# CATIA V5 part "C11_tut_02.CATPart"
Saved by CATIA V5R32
Part number: Part2
Material "Grey Blue": density 7860 kg/m3, Young's modulus 2e+11 Pa, Poisson ratio 0.266
Bounding box of the stored display mesh (mm): x 0 to 175, y -36.636 to 105, z 0 to 36.66
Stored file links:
  D:\PROJECTS\Project 2022\CATIA V5 6R 2022\Resources\Tutorial Files\c11_catia_v5_6r2022_tut\C11_tut_02.CATPart
  C:\Program Files\Dassault Systemes\B32\win_b64\startup\materials\brushed_metal2.jpg
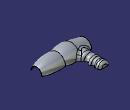
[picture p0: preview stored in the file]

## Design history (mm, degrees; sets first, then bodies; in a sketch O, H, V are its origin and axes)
Body1 (main body), material "Grey Blue"
  Plane1: type Offset, RefPlane yz-plane, Offset 50
  Set1
    Plane2: type Offset, RefPlane yz-plane, Offset 100 {= Plane1.Offset+`Plane2.Relative Offset`}
    Plane3: type Offset, RefPlane yz-plane, Offset 175
  Sketch1 on yz-plane, origin (0, 0, 0), H (0, 1, 0), V (0, 0, 1)
    arc A1 centre (0, 0) radius 25 from (25, 0) to (-25, 0) ccw
    point P1 (-25, 0)
    radius A1 = 25
  Sketch2 on Plane1, origin (50, 0, 0), H (0, 1, 0), V (0, 0, 1)
    arc A1 centre (0, 0) radius 35 from (35, 0) to (-35, 0) ccw
    point P1 (-35, 0)
    radius A1 = 35
  Sketch3 on Plane2, origin (100, 0, 0), H (0, 1, 0), V (0, 0, 1)
    arc A1 centre (0, 0) radius 30 from (30, 0) to (-30, 0) ccw
    point P1 (-30, 0)
    radius A1 = 30
  Sketch4 on Plane3, origin (175, 0, 0), H (0, 1, 0), V (0, 0, 1)
    arc A1 centre (0, 0) radius 20 from (20, 0) to (-20, 0) ccw
    point P1 (-20, 0)
    radius A1 = 20
  Sketch5 on xy-plane, origin (0, 0, 0), H (1, 0, 0), V (0, 1, 0)
    point P1 (0, -25)
    line L1 (0, -25) -> (50, -35)
    point P2 (50, -35)
    reference projected point E1 (50, -35) from Sketch2.P1
    reference projected point E2 (0, -25) from Sketch1.P1
    arc A1 centre (66.816, 49.3399) radius 86 from (50, -35) to (100, -30) ccw
    point P4 (100, -30)
    reference projected point E3 (100, -30) from Sketch3.P1
    arc A2 centre (121.7543, 93.0924) radius 125 from (100, -30) to (175, -20) ccw
    point P6 (175, -20)
    reference projected point E4 (175, -20) from Sketch4.P1
    radius A1 = 86
    radius A2 = 125
    coincidence: P1 V, P2 E1, P1 E2, P4 E3, E4 P6
  Sketch6 on xy-plane, origin (0, 0, 0), H (1, 0, 0), V (0, 1, 0)
    arc A1 centre (121.7543, -93.0924) radius 125 from (100, 30) to (175, 20) cw
    arc A2 centre (66.816, -49.3399) radius 86 from (50, 35) to (100, 30) cw
    line L1 (0, 25) -> (50, 35)
    fix: A1, L1, A2
  Loft1: Sections (Sketch1; Sketch2; Sketch3; Sketch4), Guides (Sketch5; Sketch6)
  Sketch7 on xy-plane, origin (0, 0, 0), H (1, 0, 0), V (0, 1, 0)
    point P1 (15, 105)
    line L1 (15, 105) -> (15, 0)
    point P2 (15, 0)
    point P3 (15, 105)
    distance H P1 = 105
    distance V L1 = 15
    coincidence: P2 H, P3 P1
    vertical: L1 V
  Plane4: type Normal, Curve Sketch7, RefPoint Sketch7.P3, Ratio 0
  Sketch8 on Plane4, origin (0, 105, 0), H (1, 0, 0), V (0, 0, 1)
    arc A1 centre (32.5, 0) radius 17.5 from (15, 0) to (50, 0) cw
    point P1 (32.5, 0)
    point P2 (15, 0)
    point P3 (50, 0)
    reference projected line E1 (0, 0) -> (-50, 0) from edge of Loft1
    reference projected point E2 (15, 0) from Sketch7.P2
    radius A1 = 17.5
    coincidence: P2 H, P3 H, P1 E1, E2 P2
  Sketch9 on xy-plane, origin (0, 0, 0), H (1, 0, 0), V (0, 1, 0)
    line L1 (50, 105) -> (51.989, 90.8478)
    point P1 (50, 105)
    arc A1 centre (45.0571, 89.8736) radius 7 from (51.989, 90.8478) to (49.6106, 84.5571) cw
    arc A2 centre (53.5135, 80) radius 6 from (49.6106, 84.5571) to (51.6373, 74.3009) ccw
    point P5 (53.5135, 80)
    point P6 (51.6373, 74.3009)
    arc A3 centre (50.1519, 69.7891) radius 4.75 from (51.6373, 74.3009) to (52.3972, 65.6033) cw
    point P8 (51.6373, 74.3009)
    arc A4 centre (56.6515, 57.6723) radius 9 from (52.3972, 65.6033) to (52.5866, 49.6425) ccw
    point P10 (56.6515, 57.6723)
    arc A5 centre (47.1667, 38.9362) radius 12 from (52.5866, 49.6425) to (59.0499, 40.6063) cw
    construction line L2 (50, 105) -> (61.1145, 25.9165)
    line L3 (59.0499, 40.6063) -> (64.9839, -1.6159)
    reference projected point E1 (50, 105) from Sketch8.P3
    axis line L4 (15, 105) -> (65.4512, 105)
    point P16 (15, 105)
    radius A1 = 7
    radius A2 = 6
    radius A3 = 4.75
    radius A4 = 9
    radius A5 = 12
    distance P5 P1 V = 25
    angle L4 L1 = 82
    distance P1 P16 = 35
    tangency: A2 A1, A3 L2, A3 A2, A3 A4, A5 A4, A5 L2, L3 A5, L3 L2, A1 L1
    coincidence: P8 A2, L2 L1, P5 L2, P8 P6, P10 L2, P1 E1
    horizontal: L4 H
  Loft2: Sections Sketch8, Guides (Sketch9; Sketch7)
  Trim1: Trimmed (Loft1; Loft2)
  Line1: type PtPt, FirstPoint vertex [face of Loft1], SecondPoint vertex [face of Loft1]
  Line2: type PtPt, FirstPoint vertex [face of Loft2], SecondPoint vertex [face of Loft2]
  Line3: type PtPt, FirstPoint vertex [face of Loft1], SecondPoint vertex [face of Loft1]
  Fill1: Boundary (Line3; edge of Loft1)
  Fill2: Boundary (edge of Loft1; Line1)
  Fill3: Boundary (edge of Loft2; Line2)
  Join1: Elements (Fill2; Fill3; Fill1; Trim1)
  CloseSurface1: CloseElement Join1
  Fillet1: radius 8, on edge [face of CloseSurface1 | face of CloseSurface1]
  Fillet2: radius 12, on edge [face of CloseSurface1 | face of CloseSurface1]
  Shell1: ExtOffset 0, Face (face of CloseSurface1; face of CloseSurface1; face of CloseSurface1), IntOffset 1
